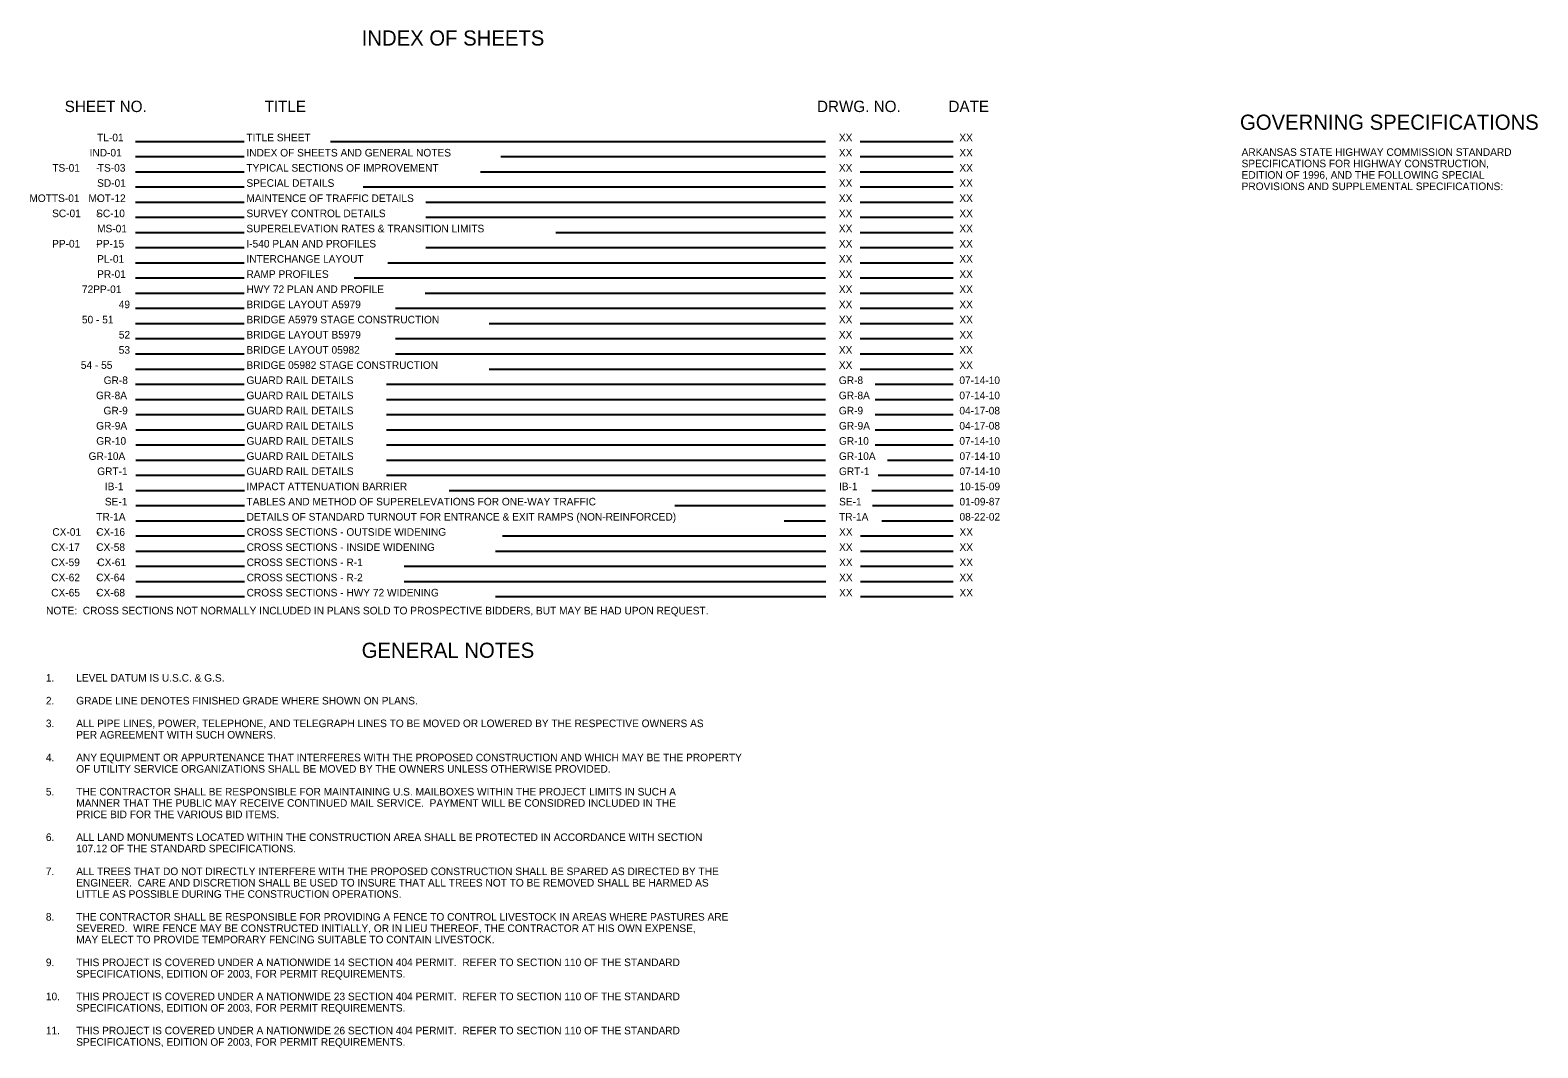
# Model space of a CAD drawing. Extents: x 1224738 to 1228169, y 151309 to 152341.
# Drawn here: x 1224738 to 1225980, y 151447 to 152286 of the extents above; entities that cross this region are included whole.
import ezdxf

# ---------------------------------------------------------------- set-up
doc = ezdxf.new("R2010")
doc.units = 0
doc.layers.add('R_Border', color=7, linetype='Continuous')

msp = doc.modelspace()

# ---------------------------------------------------------------- linework, layer by layer
at = {"layer": 'R_Border'}
for p, q in [((1224824.5, 152194), (1224914, 152194)), ((1224985, 152194), (1225392.9, 152194)), ((1225421.6, 152194), (1225498, 152194)), ((1224824.5, 152181.5), (1224914, 152181.5)), ((1225125.3, 152181.5), (1225392.9, 152181.5)), ((1225421.6, 152181.5), (1225498, 152181.5)), ((1224824.5, 152169), (1224914, 152169)), ((1225108.6, 152169), (1225392.9, 152169)), ((1225421.6, 152169), (1225498, 152169)), ((1224824.5, 152156.5), (1224914, 152156.5)), ((1225012.1, 152156.5), (1225392.9, 152156.5)), ((1225421.6, 152156.5), (1225498, 152156.5)), ((1224824.5, 152144), (1224914, 152144)), ((1225063.6, 152144), (1225392.9, 152144)), ((1225421.6, 152144), (1225498, 152144)), ((1224824.5, 152131.5), (1224914, 152131.5)), ((1225063.6, 152131.5), (1225392.9, 152131.5)), ((1225421.6, 152131.5), (1225498, 152131.5)), ((1224824.5, 152119), (1224914, 152119)), ((1225170.6, 152119), (1225392.9, 152119)), ((1225421.6, 152119), (1225498, 152119)), ((1224824.5, 152106.5), (1224914, 152106.5)), ((1225063.6, 152106.5), (1225392.9, 152106.5)), ((1225421.6, 152106.5), (1225498, 152106.5)), ((1224824.5, 152094), (1224914, 152094)), ((1225032.4, 152094), (1225392.9, 152094)), ((1225421.6, 152094), (1225498, 152094)), ((1224824.5, 152081.5), (1224914, 152081.5)), ((1225004.5, 152081.5), (1225392.9, 152081.5)), ((1225421.6, 152081.5), (1225498, 152081.5)), ((1224824.5, 152069), (1224914, 152069)), ((1225063.2, 152069), (1225392.9, 152069)), ((1225421.6, 152069), (1225498, 152069)), ((1224824.5, 152056.5), (1224914, 152056.5)), ((1225038.6, 152056.5), (1225392.9, 152056.5)), ((1225421.6, 152056.5), (1225498, 152056.5)), ((1224824.5, 152044), (1224914, 152044)), ((1225115.7, 152044), (1225392.9, 152044)), ((1225421.6, 152044), (1225498, 152044)), ((1224824.5, 152031.5), (1224914, 152031.5)), ((1225038.6, 152031.5), (1225392.9, 152031.5)), ((1225421.6, 152031.5), (1225498, 152031.5)), ((1224824.5, 152019), (1224914, 152019)), ((1225038.6, 152019), (1225392.9, 152019)), ((1225421.6, 152019), (1225498, 152019)), ((1224824.5, 152006.5), (1224914, 152006.5)), ((1225115.7, 152006.5), (1225392.9, 152006.5)), ((1225421.6, 152006.5), (1225498, 152006.5)), ((1224824.5, 151994), (1224914, 151994)), ((1225031.2, 151994), (1225392.9, 151994)), ((1225433.7, 151994), (1225498, 151994)), ((1224824.5, 151981.5), (1224914, 151981.5)), ((1225031.2, 151981.5), (1225392.9, 151981.5)), ((1225433.7, 151981.5), (1225498, 151981.5)), ((1224824.6, 151969), (1224914, 151969)), ((1225031.2, 151969), (1225392.9, 151969)), ((1225433.7, 151969), (1225498, 151969)), ((1224824.6, 151956.5), (1224914.1, 151956.5)), ((1225031.2, 151956.5), (1225392.9, 151956.5)), ((1225433.7, 151956.5), (1225498, 151956.5)), ((1224824.6, 151944), (1224914.1, 151944)), ((1225031.2, 151944), (1225392.9, 151944)), ((1225433.7, 151944), (1225498.1, 151944)), ((1224824.7, 151931.5), (1224914.1, 151931.5)), ((1225031.2, 151931.5), (1225392.9, 151931.5)), ((1225444.1, 151931.5), (1225498.1, 151931.5)), ((1224824.7, 151919), (1224914.1, 151919)), ((1225031.2, 151919), (1225392.9, 151919)), ((1225436.3, 151919), (1225498.1, 151919)), ((1224824.7, 151906.5), (1224914.1, 151906.5)), ((1225082.9, 151906.5), (1225392.9, 151906.5)), ((1225431.2, 151906.5), (1225498.1, 151906.5)), ((1224824.7, 151894), (1224914.2, 151894)), ((1225268.9, 151894), (1225392.9, 151894)), ((1225431.6, 151894), (1225498.1, 151894)), ((1224824.7, 151881.5), (1224914.2, 151881.5)), ((1225358.8, 151881.5), (1225392.9, 151881.5)), ((1225439.3, 151881.5), (1225498.1, 151881.5)), ((1224824.7, 151869), (1224914.2, 151869)), ((1225126.9, 151869), (1225393.1, 151869)), ((1225421.8, 151869), (1225498.1, 151869)), ((1224824.7, 151856.5), (1224914.2, 151856.5)), ((1225121, 151856.5), (1225393.1, 151856.5)), ((1225421.8, 151856.5), (1225498.1, 151856.5)), ((1224824.7, 151844), (1224914.2, 151844)), ((1225045.8, 151844), (1225393.1, 151844)), ((1225421.8, 151844), (1225498.1, 151844)), ((1224824.7, 151831.5), (1224914.2, 151831.5)), ((1225045.8, 151831.5), (1225393.1, 151831.5)), ((1225421.8, 151831.5), (1225498.1, 151831.5)), ((1224824.7, 151819), (1224914.2, 151819)), ((1225121, 151819), (1225393.1, 151819)), ((1225421.8, 151819), (1225498.1, 151819))]:
    msp.add_line(p, q, dxfattribs=at)

# ---------------------------------------------------------------- texts
for s, height, p in [('INDEX OF SHEETS', 12.5, (1225010.8, 152273)), ('SHEET NO.', 9.38, (1224766.1, 152218.2)), ('TITLE', 9.38, (1224930.8, 152218.2)), ('DRWG. NO.', 9.38, (1225385.9, 152218.2)), ('DATE', 9.38, (1225494.2, 152218.2)), ('GOVERNING SPECIFICATIONS', 12.5, (1225734.4, 152203.6)), ('TL-01', 6.25, (1224792.8, 152194.1)), ('TITLE SHEET', 6.25, (1224915.8, 152194.1)), ('XX', 6.25, (1225403.9, 152194.1)), ('XX', 6.25, (1225503.2, 152194.1)), ('IND-01', 6.25, (1224786.6, 152181.6)), ('INDEX OF SHEETS AND GENERAL NOTES', 6.25, (1224915.8, 152181.6)), ('XX', 6.25, (1225403.9, 152181.6)), ('XX', 6.25, (1225503.2, 152181.6)), ('ARKANSAS STATE HIGHWAY COMMISSION STANDARD ', 6.25, (1225735.7, 152182.1)), ('TS-01', 6.25, (1224755.9, 152169.1)), ('TS-03', 6.25, (1224793.4, 152169.1)), ('TYPICAL SECTIONS OF IMPROVEMENT', 6.25, (1224915.8, 152169.1)), ('XX', 6.25, (1225403.9, 152169.1)), ('XX', 6.25, (1225503.2, 152169.1)), ('SPECIFICATIONS FOR HIGHWAY CONSTRUCTION, ', 6.25, (1225735.7, 152172.7)), ('-', 6.25, (1224792, 152169.1)), ('SD-01', 6.25, (1224792.8, 152156.6)), ('SPECIAL DETAILS', 6.25, (1224915.8, 152156.6)), ('XX', 6.25, (1225403.9, 152156.6)), ('XX', 6.25, (1225503.2, 152156.6)), ('EDITION OF 1996, AND THE FOLLOWING SPECIAL ', 6.25, (1225735.7, 152163.3)), ('MOTTS-01', 6.25, (1224737, 152144.1)), ('MOT-12', 6.25, (1224785.7, 152144.1)), ('MAINTENCE OF TRAFFIC DETAILS', 6.25, (1224915.8, 152144.1)), ('XX', 6.25, (1225403.9, 152144.1)), ('XX', 6.25, (1225503.2, 152144.1)), ('PROVISIONS AND SUPPLEMENTAL SPECIFICATIONS:', 6.25, (1225735.7, 152153.9)), ('SC-01', 6.25, (1224755.7, 152131.6)), ('-', 6.25, (1224792, 152144.1)), ('SC-10', 6.25, (1224792, 152131.6)), ('SURVEY CONTROL DETAILS', 6.25, (1224915.8, 152131.6)), ('XX', 6.25, (1225403.9, 152131.6)), ('XX', 6.25, (1225503.2, 152131.6)), ('-', 6.25, (1224792, 152131.6)), ('MS-01', 6.25, (1224792.8, 152119.1)), ('SUPERELEVATION RATES & TRANSITION LIMITS', 6.25, (1224915.8, 152119.1)), ('XX', 6.25, (1225403.9, 152119.1)), ('XX', 6.25, (1225503.2, 152119.1)), ('PP-01', 6.25, (1224755.7, 152106.6)), ('PP-15', 6.25, (1224791.9, 152106.6)), ('I-540 PLAN AND PROFILES', 6.25, (1224915.8, 152106.6)), ('XX', 6.25, (1225403.9, 152106.6)), ('XX', 6.25, (1225503.2, 152106.6)), ('-', 6.25, (1224792, 152106.6)), ('PL-01', 6.25, (1224792.8, 152094.1)), ('INTERCHANGE LAYOUT', 6.25, (1224915.8, 152094.1)), ('XX', 6.25, (1225403.9, 152094.1)), ('XX', 6.25, (1225503.2, 152094.1)), ('PR-01', 6.25, (1224792.8, 152081.6)), ('RAMP PROFILES', 6.25, (1224915.8, 152081.6)), ('XX', 6.25, (1225403.9, 152081.6)), ('XX', 6.25, (1225503.2, 152081.6)), ('72PP-01', 6.25, (1224780.3, 152069.1)), ('HWY 72 PLAN AND PROFILE', 6.25, (1224915.8, 152069.1)), ('XX', 6.25, (1225403.9, 152069.1)), ('XX', 6.25, (1225503.2, 152069.1)), ('49', 6.25, (1224810.6, 152056.6)), ('BRIDGE LAYOUT A5979', 6.25, (1224915.8, 152056.6)), ('XX', 6.25, (1225403.9, 152056.6)), ('XX', 6.25, (1225503.2, 152056.6)), ('50 - 51', 6.25, (1224780.3, 152044.1)), ('BRIDGE A5979 STAGE CONSTRUCTION', 6.25, (1224915.8, 152044.1)), ('XX', 6.25, (1225403.9, 152044.1)), ('XX', 6.25, (1225503.2, 152044.1)), ('52', 6.25, (1224810.7, 152031.6)), ('BRIDGE LAYOUT B5979', 6.25, (1224915.8, 152031.6)), ('XX', 6.25, (1225403.9, 152031.6)), ('XX', 6.25, (1225503.2, 152031.6)), ('53', 6.25, (1224810.6, 152019.1)), ('BRIDGE LAYOUT 05982', 6.25, (1224915.8, 152019.1)), ('XX', 6.25, (1225403.9, 152019.1)), ('XX', 6.25, (1225503.2, 152019.1)), ('BRIDGE 05982 STAGE CONSTRUCTION', 6.25, (1224915.8, 152006.6)), ('54 - 55', 6.25, (1224779.4, 152006.6)), ('XX', 6.25, (1225403.9, 152006.6)), ('XX', 6.25, (1225503.2, 152006.6)), ('GR-8', 6.25, (1224798.2, 151994.1)), ('GUARD RAIL DETAILS', 6.25, (1224915.8, 151994.1)), ('GR-8', 6.25, (1225403.9, 151994.1)), ('07-14-10', 6.25, (1225503.2, 151994.1)), ('GR-8A', 6.25, (1224791.9, 151981.6)), ('GUARD RAIL DETAILS', 6.25, (1224915.8, 151981.6)), ('GR-8A', 6.25, (1225403.9, 151981.6)), ('07-14-10', 6.25, (1225503.2, 151981.6)), ('GR-9', 6.25, (1224798.1, 151969.1)), ('GUARD RAIL DETAILS', 6.25, (1224915.8, 151969.1)), ('GR-9', 6.25, (1225403.9, 151969.1)), ('04-17-08', 6.25, (1225503.2, 151969.1)), ('GR-9A', 6.25, (1224792, 151956.6)), ('GUARD RAIL DETAILS', 6.25, (1224915.8, 151956.6)), ('GR-9A', 6.25, (1225404, 151956.6)), ('04-17-08', 6.25, (1225503.2, 151956.6)), ('GR-10', 6.25, (1224792.1, 151944.1)), ('GUARD RAIL DETAILS', 6.25, (1224915.9, 151944.1)), ('GR-10', 6.25, (1225404, 151944.1)), ('07-14-10', 6.25, (1225503.2, 151944.1)), ('GR-10A', 6.25, (1224785.8, 151931.6)), ('GUARD RAIL DETAILS', 6.25, (1224915.9, 151931.6)), ('GR-10A', 6.25, (1225404, 151931.6)), ('07-14-10', 6.25, (1225503.3, 151931.6)), ('GRT-1', 6.25, (1224792.9, 151919.1)), ('GUARD RAIL DETAILS', 6.25, (1224915.9, 151919.1)), ('GRT-1', 6.25, (1225404, 151919.1)), ('07-14-10', 6.25, (1225503.3, 151919.1)), ('IB-1', 6.25, (1224799.2, 151906.6)), ('IMPACT ATTENUATION BARRIER', 6.25, (1224915.9, 151906.6)), ('IB-1', 6.25, (1225404, 151906.6)), ('10-15-09', 6.25, (1225503.3, 151906.6)), ('SE-1', 6.25, (1224799.2, 151894.1)), ('TABLES AND METHOD OF SUPERELEVATIONS FOR ONE-WAY TRAFFIC', 6.25, (1224915.9, 151894.1)), ('SE-1', 6.25, (1225404.1, 151894.1)), ('01-09-87', 6.25, (1225503.3, 151894.1)), ('TR-1A', 6.25, (1224792.1, 151881.6)), ('DETAILS OF STANDARD TURNOUT FOR ENTRANCE & EXIT RAMPS (NON-REINFORCED)', 6.25, (1224916, 151881.6)), ('TR-1A', 6.25, (1225404.1, 151881.6)), ('08-22-02', 6.25, (1225503.3, 151881.6)), ('CX-01', 6.25, (1224755.9, 151869.1)), ('CX-16', 6.25, (1224792.1, 151869.1)), ('-', 6.25, (1224792.1, 151869.1)), ('CROSS SECTIONS - OUTSIDE WIDENING', 6.25, (1224916, 151869.1)), ('XX', 6.25, (1225404.1, 151869.1)), ('XX', 6.25, (1225503.3, 151869.1)), ('CX-17', 6.25, (1224754.9, 151856.6)), ('CX-58', 6.25, (1224792.1, 151856.6)), ('-', 6.25, (1224792.1, 151856.6)), ('CROSS SECTIONS - INSIDE WIDENING', 6.25, (1224916, 151856.6)), ('XX', 6.25, (1225404.1, 151856.6)), ('XX', 6.25, (1225503.3, 151856.6)), ('CX-59', 6.25, (1224754.9, 151844.1)), ('-', 6.25, (1224792.1, 151844.1)), ('CX-61', 6.25, (1224793, 151844.1)), ('CROSS SECTIONS - R-1', 6.25, (1224916, 151844.1)), ('XX', 6.25, (1225404.1, 151844.1)), ('XX', 6.25, (1225503.3, 151844.1)), ('CX-62', 6.25, (1224755, 151831.6)), ('CX-64', 6.25, (1224792.1, 151831.6)), ('-', 6.25, (1224792.1, 151831.6)), ('CROSS SECTIONS - R-2', 6.25, (1224916, 151831.6)), ('XX', 6.25, (1225404.1, 151831.6)), ('XX', 6.25, (1225503.3, 151831.6)), ('CX-65', 6.25, (1224755, 151819.1)), ('CX-68', 6.25, (1224792.1, 151819.1)), ('-', 6.25, (1224792.1, 151819.1)), ('CROSS SECTIONS - HWY 72 WIDENING', 6.25, (1224916, 151819.1)), ('XX', 6.25, (1225404.1, 151819.1)), ('XX', 6.25, (1225503.3, 151819.1)), ('NOTE:  CROSS SECTIONS NOT NORMALLY INCLUDED IN PLANS SOLD TO PROSPECTIVE BIDDERS, BUT MAY BE HAD UPON REQUEST.', 6.25, (1224750.8, 151804.3)), ('GENERAL NOTES', 12.5, (1225010.8, 151768.5)), ('1.', 6.25, (1224750.6, 151748.9)), ('LEVEL DATUM IS U.S.C. & G.S.', 6.25, (1224775.6, 151748.9)), ('2.', 6.25, (1224750.6, 151730.1)), ('GRADE LINE DENOTES FINISHED GRADE WHERE SHOWN ON PLANS.', 6.25, (1224775.6, 151730.1)), ('3.', 6.25, (1224750.6, 151711.4)), ('ALL PIPE LINES, POWER, TELEPHONE, AND TELEGRAPH LINES TO BE MOVED OR LOWERED BY THE RESPECTIVE OWNERS AS ', 6.25, (1224775.6, 151711.4)), ('PER AGREEMENT WITH SUCH OWNERS.', 6.25, (1224775.6, 151702)), ('4.', 6.25, (1224750.6, 151683.3)), ('ANY EQUIPMENT OR APPURTENANCE THAT INTERFERES WITH THE PROPOSED CONSTRUCTION AND WHICH MAY BE THE PROPERTY ', 6.25, (1224775.6, 151683.3)), ('OF UTILITY SERVICE ORGANIZATIONS SHALL BE MOVED BY THE OWNERS UNLESS OTHERWISE PROVIDED.', 6.25, (1224775.6, 151673.9)), ('5.', 6.25, (1224750.6, 151655.1)), ('THE CONTRACTOR SHALL BE RESPONSIBLE FOR MAINTAINING U.S. MAILBOXES WITHIN THE PROJECT LIMITS IN SUCH A ', 6.25, (1224775.6, 151655.1)), ('MANNER THAT THE PUBLIC MAY RECEIVE CONTINUED MAIL SERVICE.  PAYMENT WILL BE CONSIDRED INCLUDED IN THE ', 6.25, (1224775.6, 151645.8)), ('PRICE BID FOR THE VARIOUS BID ITEMS.', 6.25, (1224775.6, 151636.4)), ('6.', 6.25, (1224750.6, 151617.6)), ('ALL LAND MONUMENTS LOCATED WITHIN THE CONSTRUCTION AREA SHALL BE PROTECTED IN ACCORDANCE WITH SECTION ', 6.25, (1224775.6, 151617.6)), ('107.12 OF THE STANDARD SPECIFICATIONS.', 6.25, (1224775.6, 151608.3)), ('7.', 6.25, (1224750.6, 151589.5)), ('ALL TREES THAT DO NOT DIRECTLY INTERFERE WITH THE PROPOSED CONSTRUCTION SHALL BE SPARED AS DIRECTED BY THE ', 6.25, (1224775.6, 151589.5)), ('ENGINEER.  CARE AND DISCRETION SHALL BE USED TO INSURE THAT ALL TREES NOT TO BE REMOVED SHALL BE HARMED AS ', 6.25, (1224775.6, 151580.1)), ('LITTLE AS POSSIBLE DURING THE CONSTRUCTION OPERATIONS.', 6.25, (1224775.6, 151570.8)), ('8.', 6.25, (1224750.6, 151552)), ('THE CONTRACTOR SHALL BE RESPONSIBLE FOR PROVIDING A FENCE TO CONTROL LIVESTOCK IN AREAS WHERE PASTURES ARE ', 6.25, (1224775.6, 151552)), ('SEVERED.  WIRE FENCE MAY BE CONSTRUCTED INITIALLY, OR IN LIEU THEREOF, THE CONTRACTOR AT HIS OWN EXPENSE, ', 6.25, (1224775.6, 151542.6)), ('MAY ELECT TO PROVIDE TEMPORARY FENCING SUITABLE TO CONTAIN LIVESTOCK.', 6.25, (1224775.6, 151533.3)), ('9.', 6.25, (1224750.6, 151514.5)), ('THIS PROJECT IS COVERED UNDER A NATIONWIDE 14 SECTION 404 PERMIT.  REFER TO SECTION 110 OF THE STANDARD ', 6.25, (1224775.6, 151514.5)), ('SPECIFICATIONS, EDITION OF 2003, FOR PERMIT REQUIREMENTS.', 6.25, (1224775.6, 151505.1)), ('10.', 6.25, (1224750.6, 151486.4)), ('THIS PROJECT IS COVERED UNDER A NATIONWIDE 23 SECTION 404 PERMIT.  REFER TO SECTION 110 OF THE STANDARD ', 6.25, (1224775.6, 151486.4)), ('SPECIFICATIONS, EDITION OF 2003, FOR PERMIT REQUIREMENTS.', 6.25, (1224775.6, 151477)), ('11.', 6.25, (1224750.6, 151458.3)), ('THIS PROJECT IS COVERED UNDER A NATIONWIDE 26 SECTION 404 PERMIT.  REFER TO SECTION 110 OF THE STANDARD ', 6.25, (1224775.6, 151458.3)), ('SPECIFICATIONS, EDITION OF 2003, FOR PERMIT REQUIREMENTS.', 6.25, (1224775.6, 151448.9))]:
    msp.add_text(s, height=height, dxfattribs=at).set_placement(p)

doc.saveas('drawing.dxf')
